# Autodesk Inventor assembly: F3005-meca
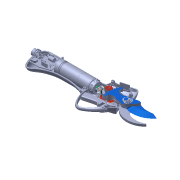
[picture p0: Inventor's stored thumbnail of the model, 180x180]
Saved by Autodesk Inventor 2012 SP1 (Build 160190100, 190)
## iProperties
Created: 2014-12
Part Number: F3005-meca
Document SubType Name: Assembly
Designer: Bruno
Author: Bruno
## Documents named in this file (6)
- D:\Cours\Systèmes\secateur-hydrogene-Pragma\Documentation\Dossier technique Infaco F3005\Solidworks\Composants importés\F3005-meca.iam
- D:\Cours\Systèmes\secateur-hydrogene-Pragma\Documentation\Dossier technique Infaco F3005\Solidworks\Composants importés\F3005-bati.iam
- D:\Cours\Systèmes\secateur-hydrogene-Pragma\Documentation\Dossier technique Infaco F3005\Solidworks\Composants importés\F3005\Gachette.ipt
- D:\Cours\Systèmes\secateur-hydrogene-Pragma\Documentation\Dossier technique Infaco F3005\Solidworks\Composants importés\F3005-lame-mobile.iam
- D:\Cours\Systèmes\secateur-hydrogene-Pragma\Documentation\Dossier technique Infaco F3005\Solidworks\Composants importés\F3005--pignon-intermédiaire.iam
- D:\Cours\Systèmes\secateur-hydrogene-Pragma\Documentation\Dossier technique Infaco F3005\Solidworks\Composants importés\F3005-arbre-moteur.iam
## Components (5 placed, 5 different names)
1. F3005-bati:1 [sub-assembly] — Placage:1, Placage:2, Logement:1, Placage:3, Placage:4, Placage:5, Placage:6
2. Gachette:1 — Placage:1, Placage:2
3. F3005-lame-mobile:1 [sub-assembly] — Logement:1
4. F3005--pignon-intermédiaire:1 [sub-assembly] — Placage:3, Placage:4
5. F3005-arbre-moteur:1 [sub-assembly] — Placage:5, Placage:6
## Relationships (7: Mate 6, Insert 1)
- Placage:1 [Mate]: F3005-bati:1 ↔ Gachette:1
- Placage:2 [Mate]: F3005-bati:1 ↔ Gachette:1
- Logement:1 [Insert]: F3005-bati:1 ↔ F3005-lame-mobile:1
- Placage:3 [Mate]: F3005-bati:1 ↔ F3005--pignon-intermédiaire:1
- Placage:4 [Mate]: F3005-bati:1 ↔ F3005--pignon-intermédiaire:1
- Placage:5 [Mate]: F3005-bati:1 ↔ F3005-arbre-moteur:1
- Placage:6 [Mate]: F3005-bati:1 ↔ F3005-arbre-moteur:1
